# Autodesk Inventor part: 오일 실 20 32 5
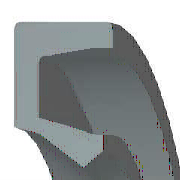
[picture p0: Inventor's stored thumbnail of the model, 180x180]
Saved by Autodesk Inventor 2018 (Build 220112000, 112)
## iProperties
IsCustomPart: 1
Created: 2012-02
Part Number: 오일 실 20 32 5
Material: 고무
Description: 오일 실 - 비스프링, 금속 케이스 GM
Document SubType Name: Modeling
Standard: JIS B 2402
Designer: mdu-01
Standards Organization: JIS
Language: ko-KR
Size Designation: 20 32 5 A
Categories: <MemberInstance><Categories><Category DisplayName="샤프트 부품" InternalName="7f7aeb1f-a693-4053-b835-cee3144e0d98" Mnemonic="SHFT"><Category DisplayName="실링" Intern
Density: 0.93 g/cm^3
Appearance: Rubber-Black
Author: mdu-01
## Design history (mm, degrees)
body "Solid1"
revolve "회전1" stored, may be unused: angle "d27" = 360 deg
fillet "모깎기1" dims "d28" = 0.25 (= 0.05 x b)
chamfer "모따기1" distance "d29" = 0.07143 (= 0.0142857 x b); stored, may be unused: second distance "d30" = 0.25 (= 0.05 x b), angle "d35" = 45 deg
sketch "스케치2"
  geometry: L1 (-10.8, -3.238)-(-11.6, -3.863); L2 (-10, -1.625)-(-10.8, -3.238); L3 (-10.6, -1)-(-10, -1.625); L4 (-12.6, -3.75)-(-10.6, -1); L5 (-14.175, -3.75)-(-12.6, -3.75); L6 (-15.375, -1.25)-(-14.175, -3.75); L7 (-15.375, 0)-(-15.375, -1.25); L8 (-16, 0)-(-15.375, 0); L9 (-16, -5)-(-16, 0); L10 (-12.427, -5)-(-16, -5); L11 (-11.6, -3.863)-(-12.427, -5); L12 (0, -9.6)-(0, 1.6) reference; L13 (-14, 0)-(-28, 0) reference
  constraints: 22 end point, 3 horizontal, 2 vertical, 1 parallel
  dimensions: "d2" = 5 distance of L9.start L8.start (= b); "d4" = 1 vertical distance of L8.start L3.start (= 0.2 x b); "d6" = 0.625 distance of L8.start L7.start (= 0.125 x b); "d8" = 1.25 distance of L7.start L6.start (= 0.25 x b); "d10" = 1.25 vertical distance of L5.start L9.start (= 0.25 x b); "d12" = 1.2 horizontal distance of L6.start L5.start (= 0.1 x dd - 0.1 x Diam); "d14" = 1.6129 vertical distance of L2.start L1.start (= 0.322581 x b); "d16" = 0.8 horizontal distance of L1.start L1.end (= 0.0666667 x dd - 0.0666667 x Diam); "d18" = 0.8 horizontal distance of L2.start L1.start (= 0.0666667 x dd - 0.0666667 x Diam); "d20" = 0.625 vertical distance of L3.start L2.start (= 0.125 x b); "d22" = 0.6 horizontal distance of L3.start L2.start (= 0.05 x dd - 0.05 x Diam); "d24" = 0.625 vertical distance of L1.start L1.end (= 0.125 x b); "d26" = 2 horizontal distance of L4.start L3.start (= 0.166667 x dd - 0.166667 x Diam); "d31" = 0 distance between parallel lines of L8 L13; "d32" = 16 distance between parallel lines of L12 L9 (= 0.5 x dd); "d33" = 10 distance from line of L12 L2.start (= 0.5 x Diam)
other parameters: "dd" = 32 [user parameter; used in 6 equation terms], "b" = 5 [user parameter; used in 11 equation terms], "d1" = 8 (derived), "d3" = 1.6 (derived), "d5" = 1 (derived), "d7" = 2 (derived), "d9" = 2 (derived), "d11" = 2 (derived), "d13" = 2.58065 (derived), "d15" = 1.33333 (derived), "d17" = 1.33333 (derived), "d19" = 1 (derived), "d21" = 1 (derived), "d23" = 1 (derived), "d25" = 3.33333 (derived), "d34" = 0
